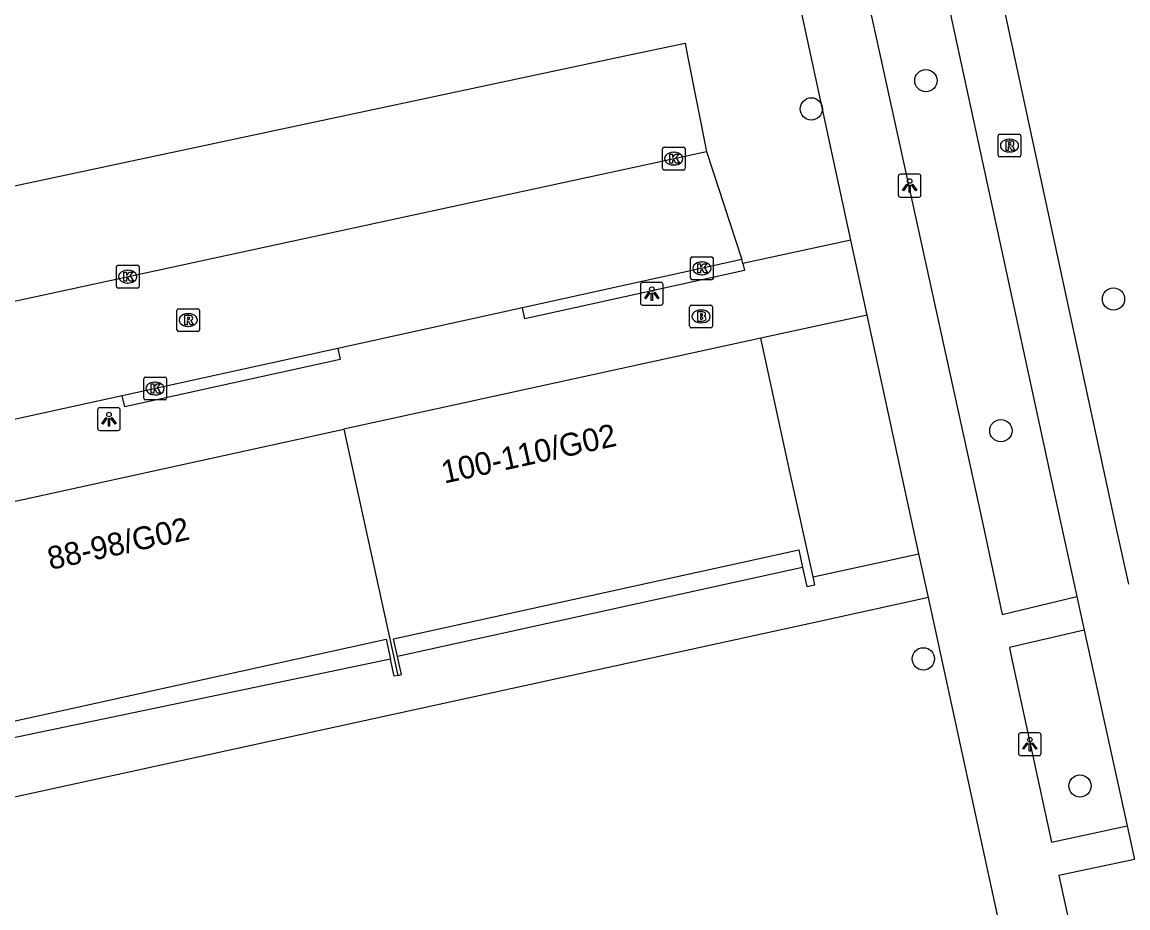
# Model space of a CAD drawing. Extents: x 160037 to 160839, y 385326 to 386441.
# Drawn here: x 160701.62 to 160750.13, y 385712.63 to 385751.48 of the extents above; entities that cross this region are included whole.
import ezdxf

# ---------------------------------------------------------------- set-up
doc = ezdxf.new("R2010")
doc.units = 0
for name, color, linetype in [('IMGEO_Boom', 7, 'Continuous'), ('IMGEO_Brandkraan', 7, 'Continuous'), ('IMGEO_Fietspad_gesloten', 7, 'Continuous'), ('IMGEO_Kolk', 7, 'Continuous'), ('IMGEO_Lichtpunt', 7, 'Continuous'), ('IMGEO_Pand', 7, 'Continuous'), ('IMGEO_Pand_nummerreeks', 7, 'Continuous'), ('IMGEO_Parkeervlak_open', 7, 'Continuous'), ('IMGEO_Rijbaan_lokaal_open', 7, 'Continuous'), ('IMGEO_Rioolput', 7, 'Continuous'), ('IMGEO_Voetpad_open', 7, 'Continuous')]:
    doc.layers.add(name, color=color, linetype=linetype)

msp = doc.modelspace()

# ---------------------------------------------------------------- linework, layer by layer
at = {"layer": 'IMGEO_Boom'}
for centre in [(160741.271, 385748.918), (160736.245, 385747.676), (160749.502, 385739.337), (160744.561, 385733.559), (160741.159, 385723.551), (160748.031, 385717.976)]:
    msp.add_circle(centre, 0.489, dxfattribs=at)
at = {"layer": 'IMGEO_Brandkraan'}
for p, q in [((160730.908, 385738.145), (160730.908, 385738.997)), ((160730.983, 385739.071), (160731.835, 385739.071)), ((160731.909, 385738.997), (160731.909, 385738.145)), ((160731.396, 385738.851), (160731.421, 385738.851)), ((160731.835, 385738.071), (160730.983, 385738.071)), ((160731.419, 385738.291), (160731.394, 385738.291))]:
    msp.add_line(p, q, dxfattribs=at)
for points in [[(160730.908, 385738.145), (160730.908, 385738.997)], [(160730.983, 385739.071), (160731.835, 385739.071)], [(160731.909, 385738.997), (160731.909, 385738.145)], [(160731.256, 385738.771), (160731.256, 385738.371), (160731.469, 385738.371)], [(160731.487, 385738.771), (160731.256, 385738.771)], [(160731.435, 385738.69), (160731.381, 385738.69), (160731.381, 385738.614)], [(160731.381, 385738.614), (160731.434, 385738.614)], [(160731.443, 385738.538), (160731.381, 385738.538), (160731.381, 385738.457)], [(160731.835, 385738.071), (160730.983, 385738.071)], [(160731.381, 385738.457), (160731.443, 385738.457)]]:
    msp.add_lwpolyline(points, dxfattribs=at)
for centre, radius, start, end in [((160730.985, 385738.995), 0.0765, 91.552, 178.448), ((160730.985, 385738.995), 0.0765, 91.552, 178.448), ((160731.833, 385738.995), 0.0765, 1.552, 88.448), ((160731.833, 385738.995), 0.0765, 1.552, 88.448), ((160731.436, 385738.652), 0.0379, 267.8285, 90.9355), ((160731.444, 385738.497), 0.0404, 269.8759, 90.5077), ((160731.491, 385738.626), 0.145, 59.4692, 91.5367), ((160731.516, 385738.673), 0.0922, 285.5137, 58.1501), ((160731.521, 385738.481), 0.105, 301.3115, 78.989), ((160730.985, 385738.147), 0.0765, 181.552, 268.448), ((160730.985, 385738.147), 0.0765, 181.552, 268.448), ((160731.475, 385738.622), 0.251, 268.6676, 293.5347), ((160731.833, 385738.147), 0.0765, 271.552, 358.448), ((160731.833, 385738.147), 0.0765, 271.552, 358.448)]:
    msp.add_arc(centre, radius, start, end, dxfattribs=at)
for centre, major_axis, ratio, start_param, end_param in [((160731.395, 385738.571), (-0.387, 0.002), 0.722429, 4.712389, 7.853982), ((160731.42, 385738.571), (-0.39, 0.002), 0.717154, 1.570796, 4.712389)]:
    msp.add_ellipse(centre, major_axis=major_axis, ratio=ratio, start_param=start_param, end_param=end_param, dxfattribs=at)
at = {"layer": 'IMGEO_Fietspad_gesloten'}
for points in [[(160750.169, 385726.821), (160749.555, 385729.594), (160740.465, 385771.775)], [(160738.146, 385771.263), (160747.021, 385730.295), (160747.898, 385726.284)], [(160747.898, 385726.284), (160748.22, 385724.812)], [(160748.22, 385724.812), (160750.096, 385716.226)], [(160750.096, 385716.226), (160750.418, 385714.749)]]:
    msp.add_lwpolyline(points, dxfattribs=at)
at = {"layer": 'IMGEO_Kolk'}
for p, q in [((160729.71, 385745.07), (160729.71, 385745.922)), ((160729.785, 385745.996), (160730.637, 385745.996)), ((160730.198, 385745.776), (160730.223, 385745.776)), ((160730.711, 385745.922), (160730.711, 385745.07)), ((160730.637, 385744.996), (160729.785, 385744.996)), ((160730.221, 385745.216), (160730.196, 385745.216)), ((160730.945, 385740.255), (160730.945, 385741.107)), ((160731.02, 385741.181), (160731.872, 385741.181)), ((160731.433, 385740.961), (160731.458, 385740.961)), ((160731.946, 385741.107), (160731.946, 385740.255)), ((160705.757, 385739.891), (160705.757, 385740.743)), ((160705.832, 385740.817), (160706.684, 385740.817)), ((160706.245, 385740.597), (160706.27, 385740.597)), ((160706.758, 385740.743), (160706.758, 385739.891)), ((160706.268, 385740.037), (160706.243, 385740.037)), ((160731.872, 385740.181), (160731.02, 385740.181)), ((160731.456, 385740.401), (160731.431, 385740.401)), ((160706.684, 385739.817), (160705.832, 385739.817)), ((160706.956, 385734.985), (160706.956, 385735.837)), ((160707.031, 385735.911), (160707.883, 385735.911)), ((160707.444, 385735.691), (160707.469, 385735.691)), ((160707.957, 385735.837), (160707.957, 385734.985)), ((160707.467, 385735.131), (160707.442, 385735.131)), ((160707.883, 385734.911), (160707.031, 385734.911))]:
    msp.add_line(p, q, dxfattribs=at)
for points in [[(160729.71, 385745.07), (160729.71, 385745.922)], [(160729.785, 385745.996), (160730.637, 385745.996)], [(160730.711, 385745.922), (160730.711, 385745.07)], [(160730.031, 385745.696), (160730.154, 385745.696), (160730.154, 385745.545), (160730.284, 385745.696), (160730.448, 385745.696), (160730.302, 385745.545), (160730.455, 385745.296), (160730.303, 385745.296), (160730.218, 385745.46), (160730.154, 385745.393), (160730.154, 385745.296), (160730.031, 385745.296), (160730.031, 385745.696)], [(160730.637, 385744.996), (160729.785, 385744.996)], [(160730.945, 385740.255), (160730.945, 385741.107)], [(160731.02, 385741.181), (160731.872, 385741.181)], [(160731.946, 385741.107), (160731.946, 385740.255)], [(160705.757, 385739.891), (160705.757, 385740.743)], [(160705.832, 385740.817), (160706.684, 385740.817)], [(160706.078, 385740.517), (160706.201, 385740.517), (160706.201, 385740.366), (160706.331, 385740.517), (160706.495, 385740.517), (160706.349, 385740.366), (160706.502, 385740.117), (160706.35, 385740.117), (160706.265, 385740.281), (160706.201, 385740.214), (160706.201, 385740.117), (160706.078, 385740.117), (160706.078, 385740.517)], [(160706.758, 385740.743), (160706.758, 385739.891)], [(160731.266, 385740.881), (160731.389, 385740.881), (160731.389, 385740.73), (160731.519, 385740.881), (160731.683, 385740.881), (160731.537, 385740.73), (160731.69, 385740.481), (160731.538, 385740.481), (160731.453, 385740.645), (160731.389, 385740.578), (160731.389, 385740.481), (160731.266, 385740.481), (160731.266, 385740.881)], [(160731.872, 385740.181), (160731.02, 385740.181)], [(160706.684, 385739.817), (160705.832, 385739.817)], [(160706.956, 385734.985), (160706.956, 385735.837)], [(160707.031, 385735.911), (160707.883, 385735.911)], [(160707.277, 385735.611), (160707.4, 385735.611), (160707.4, 385735.46), (160707.53, 385735.611), (160707.694, 385735.611), (160707.548, 385735.46), (160707.701, 385735.211), (160707.549, 385735.211), (160707.464, 385735.375), (160707.4, 385735.308), (160707.4, 385735.211), (160707.277, 385735.211), (160707.277, 385735.611)], [(160707.957, 385735.837), (160707.957, 385734.985)], [(160707.883, 385734.911), (160707.031, 385734.911)]]:
    msp.add_lwpolyline(points, dxfattribs=at)
for centre, start, end in [((160729.787, 385745.92), 91.552, 178.448), ((160729.787, 385745.92), 91.552, 178.448), ((160730.635, 385745.92), 1.552, 88.448), ((160730.635, 385745.92), 1.552, 88.448), ((160729.787, 385745.072), 181.552, 268.448), ((160729.787, 385745.072), 181.552, 268.448), ((160730.635, 385745.072), 271.552, 358.448), ((160730.635, 385745.072), 271.552, 358.448), ((160731.022, 385741.105), 91.552, 178.448), ((160731.022, 385741.105), 91.552, 178.448), ((160731.87, 385741.105), 1.552, 88.448), ((160731.87, 385741.105), 1.552, 88.448), ((160705.834, 385740.741), 91.552, 178.448), ((160705.834, 385740.741), 91.552, 178.448), ((160706.682, 385740.741), 1.552, 88.448), ((160706.682, 385740.741), 1.552, 88.448), ((160731.022, 385740.257), 181.552, 268.448), ((160731.022, 385740.257), 181.552, 268.448), ((160731.87, 385740.257), 271.552, 358.448), ((160731.87, 385740.257), 271.552, 358.448), ((160705.834, 385739.893), 181.552, 268.448), ((160705.834, 385739.893), 181.552, 268.448), ((160706.682, 385739.893), 271.552, 358.448), ((160706.682, 385739.893), 271.552, 358.448), ((160707.033, 385735.835), 91.552, 178.448), ((160707.033, 385735.835), 91.552, 178.448), ((160707.881, 385735.835), 1.552, 88.448), ((160707.881, 385735.835), 1.552, 88.448), ((160707.033, 385734.987), 181.552, 268.448), ((160707.033, 385734.987), 181.552, 268.448), ((160707.881, 385734.987), 271.552, 358.448), ((160707.881, 385734.987), 271.552, 358.448)]:
    msp.add_arc(centre, 0.0765, start, end, dxfattribs=at)
for centre, major_axis, ratio, start_param, end_param in [((160730.197, 385745.496), (-0.387, 0.002), 0.722429, 4.712389, 7.853982), ((160730.222, 385745.496), (-0.39, 0.002), 0.717154, 1.570796, 4.712389), ((160731.432, 385740.681), (-0.387, 0.002), 0.722429, 4.712389, 7.853982), ((160731.457, 385740.681), (-0.39, 0.002), 0.717154, 1.570796, 4.712389), ((160706.244, 385740.317), (-0.387, 0.002), 0.722429, 4.712389, 7.853982), ((160706.269, 385740.317), (-0.39, 0.002), 0.717154, 1.570796, 4.712389), ((160707.443, 385735.411), (-0.387, 0.002), 0.722429, 4.712389, 7.853982), ((160707.468, 385735.411), (-0.39, 0.002), 0.717154, 1.570796, 4.712389)]:
    msp.add_ellipse(centre, major_axis=major_axis, ratio=ratio, start_param=start_param, end_param=end_param, dxfattribs=at)
at = {"layer": 'IMGEO_Lichtpunt'}
for p, q in [((160740.962, 385744.808), (160740.154, 385744.808)), ((160740.962, 385744.808), (160740.154, 385744.808)), ((160740.06, 385744.713), (160740.06, 385743.906)), ((160740.06, 385744.713), (160740.06, 385743.906)), ((160741.056, 385743.906), (160741.056, 385744.713)), ((160741.056, 385743.906), (160741.056, 385744.713)), ((160740.154, 385743.812), (160740.962, 385743.812)), ((160740.154, 385743.812), (160740.962, 385743.812)), ((160728.749, 385739.972), (160728.749, 385739.165)), ((160728.749, 385739.972), (160728.749, 385739.165)), ((160729.651, 385740.067), (160728.843, 385740.067)), ((160729.651, 385740.067), (160728.843, 385740.067)), ((160729.745, 385739.165), (160729.745, 385739.972)), ((160729.745, 385739.165), (160729.745, 385739.972)), ((160728.843, 385739.071), (160729.651, 385739.071)), ((160728.843, 385739.071), (160729.651, 385739.071)), ((160704.933, 385734.472), (160704.933, 385733.665)), ((160704.933, 385734.472), (160704.933, 385733.665)), ((160705.835, 385734.567), (160705.027, 385734.567)), ((160705.835, 385734.567), (160705.027, 385734.567)), ((160705.929, 385733.665), (160705.929, 385734.472)), ((160705.929, 385733.665), (160705.929, 385734.472)), ((160705.027, 385733.571), (160705.835, 385733.571)), ((160705.027, 385733.571), (160705.835, 385733.571)), ((160745.33, 385720.21), (160745.33, 385719.403)), ((160745.33, 385720.21), (160745.33, 385719.403)), ((160746.232, 385720.305), (160745.424, 385720.305)), ((160746.232, 385720.305), (160745.424, 385720.305)), ((160746.326, 385719.403), (160746.326, 385720.21)), ((160746.326, 385719.403), (160746.326, 385720.21)), ((160745.424, 385719.309), (160746.232, 385719.309)), ((160745.424, 385719.309), (160746.232, 385719.309))]:
    msp.add_line(p, q, dxfattribs=at)
for points in [[(160740.434, 385744.377), (160740.473, 385744.349), (160740.285, 385744.087), (160740.247, 385744.114), (160740.434, 385744.377)], [(160740.536, 385744.329), (160740.583, 385744.329), (160740.583, 385744.007), (160740.536, 385744.007), (160740.536, 385744.329)], [(160740.646, 385744.349), (160740.684, 385744.376), (160740.871, 385744.114), (160740.832, 385744.086), (160740.646, 385744.349)], [(160729.123, 385739.636), (160729.162, 385739.608), (160728.974, 385739.346), (160728.936, 385739.373), (160729.123, 385739.636)], [(160729.225, 385739.588), (160729.272, 385739.588), (160729.272, 385739.266), (160729.225, 385739.266), (160729.225, 385739.588)], [(160729.335, 385739.608), (160729.373, 385739.635), (160729.56, 385739.373), (160729.521, 385739.345), (160729.335, 385739.608)], [(160705.307, 385734.136), (160705.346, 385734.108), (160705.158, 385733.846), (160705.12, 385733.873), (160705.307, 385734.136)], [(160705.519, 385734.108), (160705.557, 385734.135), (160705.744, 385733.873), (160705.705, 385733.845), (160705.519, 385734.108)], [(160705.409, 385734.088), (160705.456, 385734.088), (160705.456, 385733.766), (160705.409, 385733.766), (160705.409, 385734.088)], [(160745.704, 385719.874), (160745.743, 385719.846), (160745.555, 385719.584), (160745.517, 385719.611), (160745.704, 385719.874)], [(160745.806, 385719.826), (160745.853, 385719.826), (160745.853, 385719.504), (160745.806, 385719.504), (160745.806, 385719.826)], [(160745.916, 385719.846), (160745.954, 385719.873), (160746.141, 385719.611), (160746.102, 385719.583), (160745.916, 385719.846)]]:
    msp.add_lwpolyline(points, dxfattribs=at)
for centre in [(160740.559, 385744.511), (160729.248, 385739.77), (160705.432, 385734.27), (160745.829, 385720.008)]:
    msp.add_circle(centre, 0.0994, dxfattribs=at)
for centre, start, end in [((160740.154, 385744.713), 90, 180), ((160740.154, 385744.713), 90, 180), ((160740.962, 385744.713), 0, 90), ((160740.962, 385744.713), 0, 90), ((160740.154, 385743.906), 180, 270), ((160740.154, 385743.906), 180, 270), ((160740.962, 385743.906), 270, 0), ((160740.962, 385743.906), 270, 360), ((160728.843, 385739.972), 90, 180), ((160728.843, 385739.972), 90, 180), ((160729.651, 385739.972), 0, 90), ((160729.651, 385739.972), 0, 90), ((160728.843, 385739.165), 180, 270), ((160728.843, 385739.165), 180, 270), ((160729.651, 385739.165), 270, 0), ((160729.651, 385739.165), 270, 360), ((160705.027, 385734.472), 90, 180), ((160705.027, 385734.472), 90, 180), ((160705.835, 385734.472), 0, 90), ((160705.835, 385734.472), 0, 90), ((160705.027, 385733.665), 180, 270), ((160705.027, 385733.665), 180, 270), ((160705.835, 385733.665), 270, 0), ((160705.835, 385733.665), 270, 360), ((160745.424, 385720.21), 90, 180), ((160745.424, 385720.21), 90, 180), ((160746.232, 385720.21), 0, 90), ((160746.232, 385720.21), 0, 90), ((160745.424, 385719.403), 180, 270), ((160745.424, 385719.403), 180, 270), ((160746.232, 385719.403), 270, 0), ((160746.232, 385719.403), 270, 360)]:
    msp.add_arc(centre, 0.0946, start, end, dxfattribs=at)
at = {"layer": 'IMGEO_Pand'}
for points in [[(160734.024, 385737.623), (160715.735, 385733.629)], [(160736.32, 385727.15), (160735.295, 385731.826), (160734.024, 385737.623)], [(160697.845, 385729.707), (160715.735, 385733.629)], [(160715.735, 385733.629), (160718.103, 385722.828)], [(160718.089, 385723.65), (160717.917, 385724.435), (160735.691, 385728.331), (160735.862, 385727.554)], [(160735.862, 385727.554), (160736.044, 385726.724), (160736.397, 385726.801), (160736.32, 385727.15)], [(160700.194, 385719.866), (160700.042, 385720.561), (160717.589, 385724.408), (160717.78, 385723.538)], [(160718.103, 385722.828), (160717.943, 385722.793), (160717.78, 385723.538)], [(160718.103, 385722.828), (160718.262, 385722.863), (160718.089, 385723.65)]]:
    msp.add_lwpolyline(points, dxfattribs=at)
at = {"layer": 'IMGEO_Parkeervlak_open'}
msp.add_lwpolyline([(160688.13, 385739.194), (160687.537, 385741.382), (160728.062, 385750), (160730.705, 385750.562), (160730.817, 385750), (160731.652, 385745.804)], dxfattribs=at)
at = {"layer": 'IMGEO_Rijbaan_lokaal_open'}
for points in [[(160686.598, 385736.065), (160731.652, 385745.804)], [(160731.652, 385745.804), (160733.2, 385741.066)], [(160733.2, 385741.066), (160723.574, 385738.95)], [(160723.574, 385738.95), (160715.473, 385737.171)], [(160715.473, 385737.171), (160706.015, 385735.093)], [(160706.015, 385735.093), (160697.595, 385733.243)]]:
    msp.add_lwpolyline(points, dxfattribs=at)
at = {"layer": 'IMGEO_Rioolput'}
for p, q in [((160744.438, 385745.642), (160744.438, 385746.494)), ((160744.513, 385746.568), (160745.365, 385746.568)), ((160744.926, 385746.348), (160744.951, 385746.348)), ((160745.439, 385746.494), (160745.439, 385745.642)), ((160744.949, 385745.788), (160744.924, 385745.788)), ((160745.365, 385745.568), (160744.513, 385745.568)), ((160708.41, 385737.986), (160708.41, 385738.838)), ((160708.485, 385738.912), (160709.337, 385738.912)), ((160708.898, 385738.692), (160708.923, 385738.692)), ((160709.411, 385738.838), (160709.411, 385737.986)), ((160708.921, 385738.132), (160708.896, 385738.132)), ((160709.337, 385737.912), (160708.485, 385737.912))]:
    msp.add_line(p, q, dxfattribs=at)
for points in [[(160744.438, 385745.642), (160744.438, 385746.494)], [(160744.513, 385746.568), (160745.365, 385746.568)], [(160745.027, 385746.266), (160744.775, 385746.268), (160744.775, 385745.868)], [(160745.439, 385746.494), (160745.439, 385745.642)], [(160744.775, 385745.868), (160744.899, 385745.868), (160744.899, 385746.03), (160744.91, 385746.03)], [(160744.953, 385746.187), (160744.899, 385746.187), (160744.899, 385746.106)], [(160744.899, 385746.106), (160744.951, 385746.106)], [(160744.957, 385746.001), (160745.028, 385745.868), (160745.168, 385745.868), (160745.103, 385745.994)], [(160745.365, 385745.568), (160744.513, 385745.568)], [(160708.41, 385737.986), (160708.41, 385738.838)], [(160708.485, 385738.912), (160709.337, 385738.912)], [(160708.999, 385738.61), (160708.747, 385738.612), (160708.747, 385738.212)], [(160708.925, 385738.531), (160708.871, 385738.531), (160708.871, 385738.45)], [(160709.411, 385738.838), (160709.411, 385737.986)], [(160708.747, 385738.212), (160708.871, 385738.212), (160708.871, 385738.374), (160708.882, 385738.374)], [(160708.871, 385738.45), (160708.923, 385738.45)], [(160708.929, 385738.345), (160709, 385738.212), (160709.14, 385738.212), (160709.075, 385738.338)], [(160709.337, 385737.912), (160708.485, 385737.912)]]:
    msp.add_lwpolyline(points, dxfattribs=at)
for centre, radius, start, end in [((160744.515, 385746.492), 0.0765, 91.552, 178.448), ((160744.515, 385746.492), 0.0765, 91.552, 178.448), ((160745.026, 385746.156), 0.109, 350.3612, 89.416), ((160745.363, 385746.492), 0.0765, 1.552, 88.448), ((160745.363, 385746.492), 0.0765, 1.552, 88.448), ((160744.909, 385745.977), 0.0533, 26.0293, 88.6989), ((160744.935, 385746.295), 0.19, 274.7715, 282.9687), ((160744.959, 385746.091), 0.0964, 77.0061, 93.1865), ((160744.973, 385746.148), 0.0378, 276.6634, 79.6772), ((160745.024, 385746.156), 0.112, 277.5842, 350.9817), ((160745.008, 385745.941), 0.108, 29.5134, 73.7905), ((160744.515, 385745.644), 0.0765, 181.552, 268.448), ((160744.515, 385745.644), 0.0765, 181.552, 268.448), ((160745.363, 385745.644), 0.0765, 271.552, 358.448), ((160745.363, 385745.644), 0.0765, 271.552, 358.448), ((160708.487, 385738.836), 0.0765, 91.552, 178.448), ((160708.487, 385738.836), 0.0765, 91.552, 178.448), ((160708.931, 385738.435), 0.0964, 77.0061, 93.1865), ((160708.945, 385738.492), 0.0378, 276.6634, 79.6772), ((160708.998, 385738.5), 0.109, 350.3612, 89.416), ((160708.996, 385738.5), 0.112, 277.5842, 350.9817), ((160709.335, 385738.836), 0.0765, 1.552, 88.448), ((160709.335, 385738.836), 0.0765, 1.552, 88.448), ((160708.487, 385737.988), 0.0765, 181.552, 268.448), ((160708.487, 385737.988), 0.0765, 181.552, 268.448), ((160708.881, 385738.321), 0.0533, 26.0293, 88.6989), ((160708.907, 385738.639), 0.19, 274.7715, 282.9687), ((160708.98, 385738.285), 0.108, 29.5134, 73.7905), ((160709.335, 385737.988), 0.0765, 271.552, 358.448), ((160709.335, 385737.988), 0.0765, 271.552, 358.448)]:
    msp.add_arc(centre, radius, start, end, dxfattribs=at)
for centre, major_axis, ratio, start_param, end_param in [((160744.925, 385746.068), (-0.387, 0.002), 0.722429, 4.712389, 7.853982), ((160744.95, 385746.068), (-0.39, 0.002), 0.717154, 1.570796, 4.712389), ((160708.897, 385738.412), (-0.387, 0.002), 0.722429, 4.712389, 7.853982), ((160708.922, 385738.412), (-0.39, 0.002), 0.717154, 1.570796, 4.712389)]:
    msp.add_ellipse(centre, major_axis=major_axis, ratio=ratio, start_param=start_param, end_param=end_param, dxfattribs=at)
at = {"layer": 'IMGEO_Voetpad_open'}
for points in [[(160738.146, 385771.263), (160734.764, 385770.469), (160734.938, 385769.668), (160739.258, 385750), (160743.693, 385729.807), (160744.621, 385725.495), (160747.898, 385726.284)], [(160737.979, 385741.913), (160732.939, 385765.276)], [(160737.979, 385741.913), (160733.243, 385740.892)], [(160738.688, 385738.629), (160737.979, 385741.913)], [(160733.243, 385740.892), (160733.32, 385740.581), (160723.683, 385738.463), (160723.574, 385738.95)], [(160733.243, 385740.892), (160733.2, 385741.066)], [(160738.688, 385738.629), (160734.024, 385737.623)], [(160740.965, 385728.164), (160738.688, 385738.629)], [(160715.473, 385737.171), (160715.582, 385736.684), (160706.124, 385734.606), (160706.015, 385735.093)], [(160736.32, 385727.15), (160740.965, 385728.164)], [(160741.383, 385726.239), (160740.965, 385728.164)], [(160735.862, 385727.554), (160718.089, 385723.65)], [(160741.383, 385726.239), (160736.6, 385725.195), (160682.511, 385713.385)], [(160746.478, 385702.821), (160741.383, 385726.239)], [(160748.22, 385724.812), (160744.933, 385724.043), (160744.936, 385724.029), (160745.057, 385723.467), (160746.787, 385715.509), (160750.096, 385716.226)], [(160717.78, 385723.538), (160700.194, 385719.866)], [(160750.418, 385714.749), (160747.106, 385714.042), (160747.585, 385711.838), (160748.912, 385705.94), (160756.742, 385670.124), (160764.406, 385634.512), (160767.671, 385635.207)]]:
    msp.add_lwpolyline(points, dxfattribs=at)

# ---------------------------------------------------------------- texts
at = {"layer": 'IMGEO_Pand_nummerreeks'}
for s, p in [('100-110/G02', (160720.137, 385731.236)), ('88-98/G02', (160702.859, 385727.449))]:
    msp.add_text(s, height=1, rotation=12.365, dxfattribs=at).set_placement(p)

doc.saveas('drawing.dxf')
